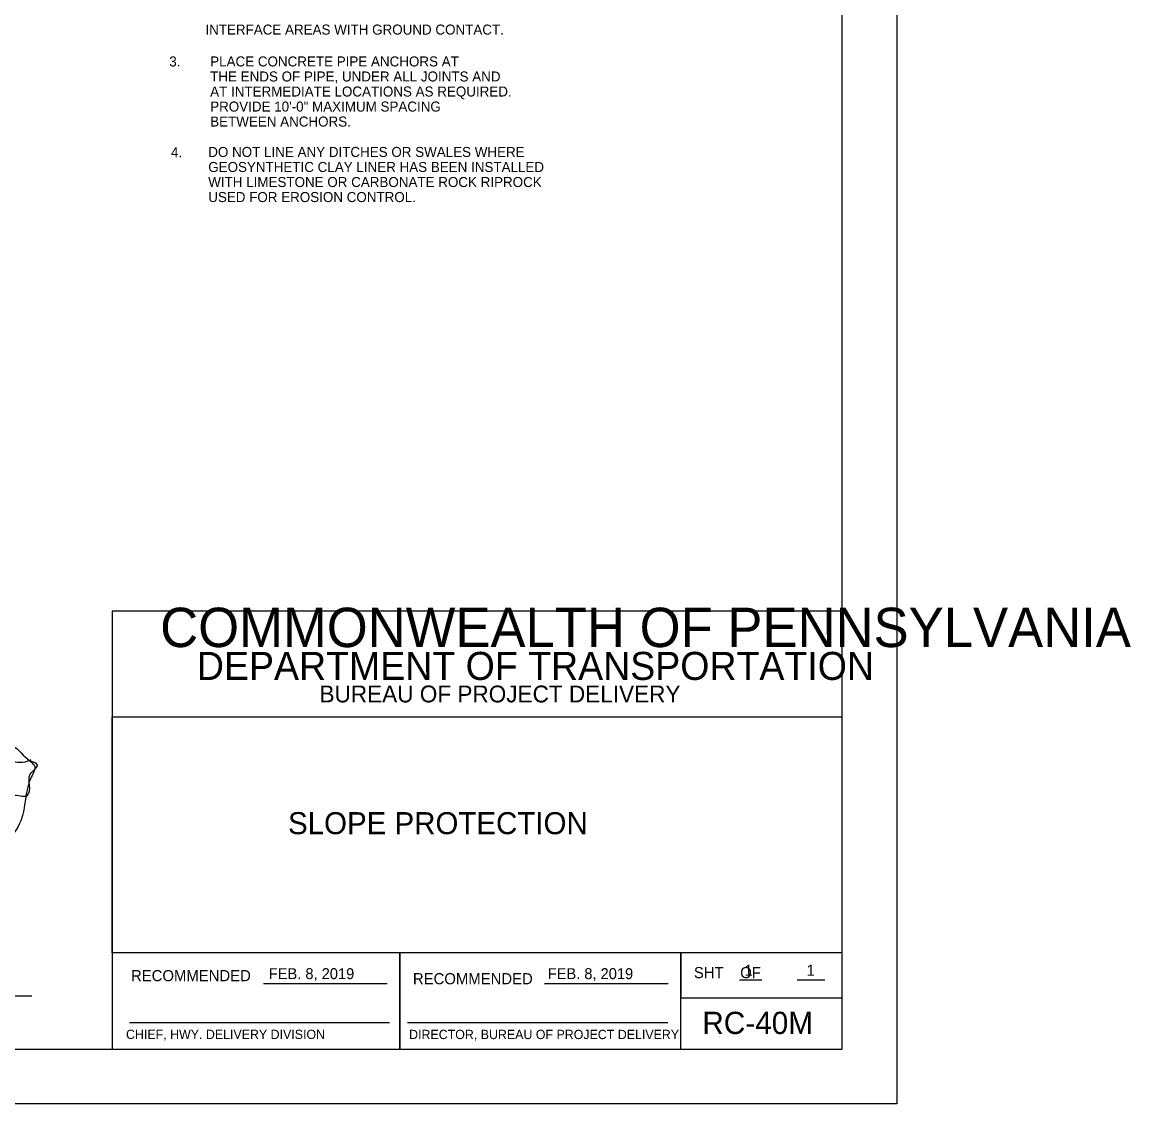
# Model space of a CAD drawing. Extents: x 5 to 910, y -47 to 547.
# Drawn here: x 606.1 to 909.8, y -46.5 to 249.8 of the extents above; entities that cross this region are included whole.
import ezdxf

# ---------------------------------------------------------------- set-up
doc = ezdxf.new("R2010")
doc.units = 0
for name, color, linetype in [('1', 7, 'Continuous'), ('2', 7, 'Continuous'), ('3', 7, 'Continuous'), ('PLT-BNDY', 7, 'Continuous')]:
    doc.layers.add(name, color=color, linetype=linetype)

msp = doc.modelspace()

# ---------------------------------------------------------------- linework, layer by layer
at = {"layer": '1'}
for p, q in [((672.18, -13.54), (706.07, -13.54)), ((749.18, -13.54), (783.05, -13.54)), ((802.58, -12.55), (808.73, -12.55)), ((818.39, -12.55), (826.04, -12.55)), ((635.48, -24.2), (706.73, -24.2)), ((711.65, -24.2), (782.99, -24.2))]:
    msp.add_line(p, q, dxfattribs=at)
msp.add_lwpolyline([(830.72, -31.53), (830.72, 532.47), (44.72, 532.47), (44.72, -31.53), (830.72, -31.53), (830.72, -5.17), (630.72, -5.17), (630.72, 59.51), (830.72, 59.51), (830.72, 88.47), (630.72, 88.47), (630.72, -31.53), (709.52, -31.53), (709.52, -5.17), (709.52, -31.53), (786.52, -31.53), (786.52, -5.17), (786.52, -17.48), (830.72, -17.48)], dxfattribs=at)
at = {"layer": '2'}
msp.add_line((608.7, -17.07), (576.87, -17.07), dxfattribs=at)
at = {"layer": '3'}
for points in [[(582.27, 46.93), (580.95, 47.36), (580.95, 48.55), (581.47, 54.96), (583.81, 55.97), (584.33, 57.13), (585.5, 58.83), (588.02, 61), (592.23, 60.84), (594.08, 59.51), (596.44, 57.32), (603.5, 51.76), (608.22, 47.36), (609.41, 46.06), (608.56, 43.02), (605.7, 31.05), (600.14, 24.33), (594.77, 22.31), (588.54, 21.81), (580.79, 24.65), (572.8, 31.85)], [(608.45, 47.73), (606.11, 47.02), (601.99, 46.49), (601.81, 45.05), (601.1, 43.61), (601.65, 41.67), (601.99, 38.44), (603.99, 38.08), (607.55, 38.08), (608.1, 40.75), (608.26, 43.8), (610.23, 46.31), (608.45, 47.36)]]:
    msp.add_spline(points, degree=3, dxfattribs=at)
at = {"layer": 'PLT-BNDY'}
msp.add_lwpolyline([(4.72, 547.47), (845.72, 547.47), (845.72, -46.53), (4.72, -46.53)], close=True, dxfattribs=at)

# ---------------------------------------------------------------- texts
at = {"layer": '1'}
for s, height, p in [('COMMONWEALTH OF PENNSYLVANIA', 10.7834, (643.87, 78.62)), ('DEPARTMENT OF TRANSPORTATION', 7.6843, (653.93, 69.62)), ('BUREAU OF PROJECT DELIVERY', 4.6221, (687.53, 63.46)), (' SLOPE PROTECTION', 6.04, (676.66, 27.35)), ('SHT    OF', 3.048, (790.12, -12.1)), ('1', 3.05, (803.95, -11.45)), ('1', 3.05, (820.99, -11.45)), ('RECOMMENDED', 3.048, (635.88, -12.93)), ('FEB. 8, 2019', 3, (673.63, -12.36)), ('RECOMMENDED', 3.048, (713.13, -13.77)), ('FEB. 8, 2019', 3, (750.06, -12.36)), ('APPROVED', 0.0192, (673.74, -13.59)), ('RC-40M', 6.096, (792.42, -27.4)), ('CHIEF, HWY. DELIVERY DIVISION', 2.54, (634.51, -28.76)), ('DIRECTOR, BUREAU OF PROJECT DELIVERY', 2.54, (712.08, -28.79))]:
    msp.add_text(s, height=height, dxfattribs=at).set_placement(p)
at = {"layer": '2'}
for s, height, p in [('INTERFACE AREAS WITH GROUND CONTACT.', 2.7454, (656.26, 246.44)), ('3.', 2.745, (646.36, 237.7)), ('PLACE CONCRETE PIPE ANCHORS AT', 2.7454, (657.57, 237.71)), ('THE ENDS OF PIPE, UNDER ALL JOINTS AND', 2.7454, (657.57, 233.59)), ('AT INTERMEDIATE LOCATIONS AS REQUIRED.', 2.7454, (657.57, 229.47)), ('PROVIDE 10\'-0" MAXIMUM SPACING', 2.7454, (657.57, 225.35)), ('BETWEEN ANCHORS.', 2.7454, (657.57, 221.24)), ('DO NOT LINE ANY DITCHES OR SWALES WHERE ', 2.7454, (657.04, 212.91)), ('4.', 2.746, (646.81, 212.81)), ('GEOSYNTHETIC CLAY LINER HAS BEEN INSTALLED ', 2.7454, (657.04, 208.79)), ('WITH LIMESTONE OR CARBONATE ROCK RIPROCK ', 2.7454, (657.04, 204.67)), ('USED FOR EROSION CONTROL.', 2.7454, (657.04, 200.55))]:
    msp.add_text(s, height=height, dxfattribs=at).set_placement(p)

doc.saveas('drawing.dxf')
